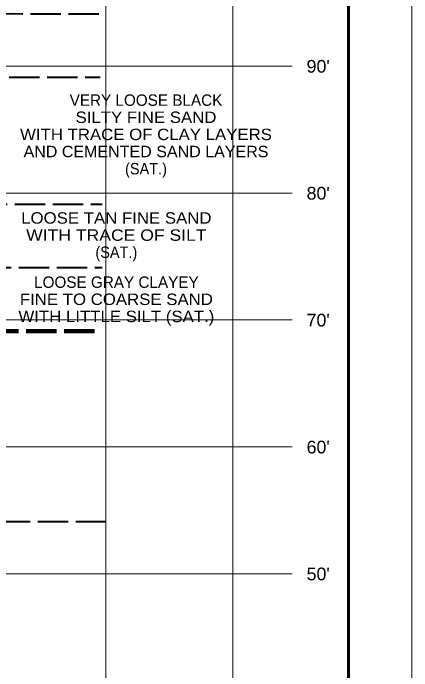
# Model space of a CAD drawing. Extents: x -582 to 653, y -817 to -3.
# Drawn here: x -133.1 to -101.6, y -263.1 to -211.3 of the extents above; entities that cross this region are included whole.
import ezdxf
from ezdxf.enums import TextEntityAlignment as Align

# ---------------------------------------------------------------- set-up
doc = ezdxf.new("R2010")
doc.units = 0
doc.header["$LTSCALE"] = 0.4
doc.linetypes.add('LONG_DASHED', pattern=[7.5, 6, -1.5])
for name, color, linetype, lineweight in [('26', 7, 'LONG_DASHED', 40), ('63', 7, 'Continuous', 35), ('7', 7, 'Continuous', 13)]:
    doc.layers.add(name, color=color, linetype=linetype, lineweight=lineweight)
doc.layers.add('29', color=7, linetype='Continuous')

msp = doc.modelspace()

# ---------------------------------------------------------------- linework, layer by layer
at = {"layer": '26'}
for points in [[(-185.2879, -215.7683), (-174.783, -215.5929), (-171.0156, -215.5929), (-168.5156, -215.5929), (-144.783, -211.343), (-141.0156, -211.343), (-138.5156, -211.343), (-126.2278, -211.343)], [(-154.1041, -218.4476), (-148.9069, -216.7927), (-144.783, -216.343), (-141.0156, -216.343), (-138.5156, -216.343), (-126.2278, -216.343)], [(-153.9467, -226.3282), (-144.783, -226.343), (-141.0156, -226.343), (-138.5156, -226.343), (-126.0703, -226.343)], [(-153.6317, -231.5293), (-144.783, -231.343), (-141.0156, -231.343), (-138.5156, -231.343), (-126.0703, -231.343)], [(-185.1304, -251.2306), (-174.783, -251.0929), (-171.0156, -251.0929), (-168.5156, -251.0929), (-144.783, -251.3429), (-141.0156, -251.3429), (-138.5156, -251.3429), (-125.834, -251.3429)]]:
    msp.add_spline(points, degree=3, dxfattribs=at)
at = {"layer": '26', "lineweight": 100}
msp.add_spline([(-185.4153, -231.0733), (-174.783, -231.0929), (-171.0156, -231.0929), (-168.5156, -231.0929), (-144.783, -236.343), (-141.0156, -236.343), (-138.5156, -236.343), (-126.0703, -236.343)], degree=3, dxfattribs=at)
at = {"layer": '63', "lineweight": 13}
msp.add_line((-101.6418, -329.4952), (-101.6418, -159.4952), dxfattribs=at)
at = {"layer": '63', "lineweight": 60}
msp.add_line((-106.6418, -164.8424), (-106.6418, -325.4952), dxfattribs=at)
at = {"layer": '7'}
for p, q in [((-125.7656, -315.4816), (-125.7656, -169.1034)), ((-115.7656, -315.4816), (-115.7656, -169.1034)), ((-134.7405, -215.4729), (-111.0807, -215.4729)), ((-134.7405, -225.4729), (-111.0807, -225.4729)), ((-134.7407, -235.4729), (-111.0807, -235.4729)), ((-134.7405, -245.4729), (-111.0807, -245.4729)), ((-134.7405, -255.4729), (-111.0807, -255.4729))]:
    msp.add_line(p, q, dxfattribs=at)

# ---------------------------------------------------------------- texts
at = {"layer": '29'}
for s, p in [('VERY LOOSE BLACK', (-122.6041, -218.5967)), ('LOOSE GRAY CLAYEY', (-124.9412, -232.9409))]:
    msp.add_text(s, height=0.9, dxfattribs=at).set_placement(p, align=Align.CENTER)
for s, width, p in [('SILTY FINE SAND', 1.1, (-122.6041, -219.9467)), ('WITH TRACE OF CLAY LAYERS', 1.1, (-122.6041, -221.2967)), ('AND CEMENTED SAND LAYERS', 1.05, (-122.6042, -222.6467)), ('(SAT.)', 0.95, (-122.6041, -223.9967)), ('LOOSE TAN FINE SAND', 1.1, (-124.9412, -227.8831)), ('WITH TRACE OF SILT', 1.15, (-124.9412, -229.2331)), ('(SAT.)', 0.95, (-124.9412, -230.5831)), ('FINE TO COARSE SAND', 1.1, (-124.9413, -234.2909)), ('WITH LITTLE SILT (SAT.)', 1.1, (-124.9413, -235.6409))]:
    msp.add_text(s, height=0.9, dxfattribs=dict(at, width=width)).set_placement(p, align=Align.CENTER)
at = {"layer": '63', "width": 1.05}
for s, p in [("90'", (-109.0274, -215.9837)), ("80'", (-109.0274, -225.9837)), ("70'", (-109.0274, -235.9837)), ("60'", (-109.0274, -245.9837)), ("50'", (-109.0274, -255.9837))]:
    msp.add_text(s, height=1, dxfattribs=at).set_placement(p, align=Align.CENTER)

doc.saveas('drawing.dxf')
